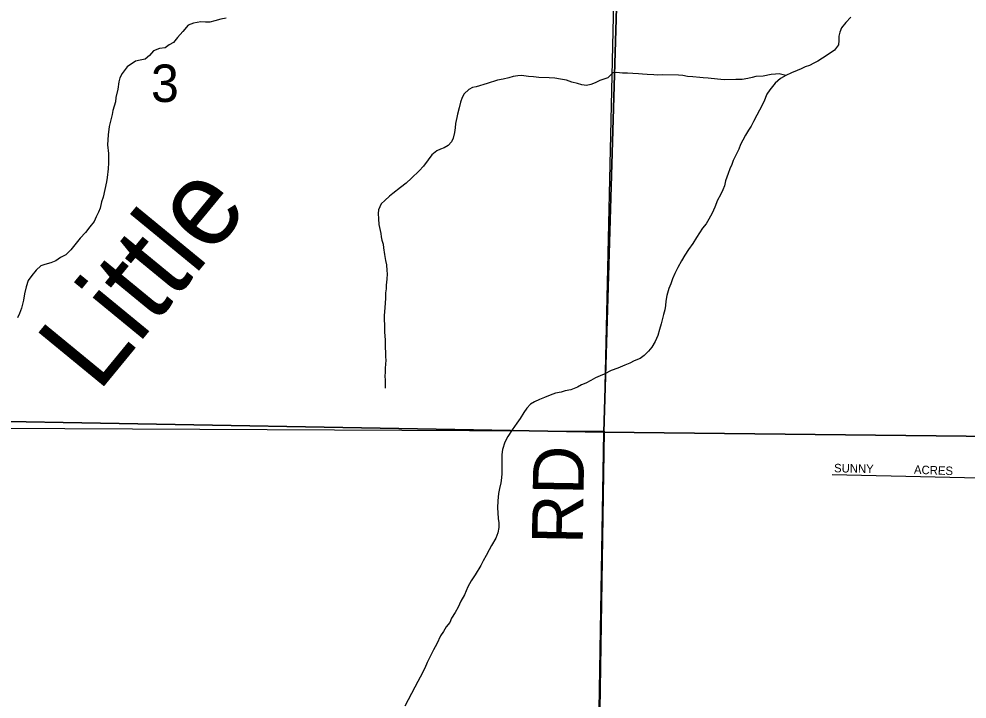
# Model space of a CAD drawing. Extents: x 1588073 to 2013523, y 1090242 to 1357120.
# Drawn here: x 1798510 to 1804101, y 1242813 to 1246824 of the extents above; entities that cross this region are included whole.
import ezdxf

# ---------------------------------------------------------------- set-up
doc = ezdxf.new("R2010")
doc.units = 0
for name, color, linetype in [('GM_X_Minor_River', 7, 'Continuous'), ('GM_X_Minor_River_Text', 7, 'Continuous'), ('GM_X_Section', 7, 'Continuous'), ('GM_X_Section_Text', 7, 'Continuous'), ('GM_X_Township', 7, 'Continuous'), ('GM_X_Township_Road', 7, 'Continuous'), ('GM_X_Township_Road_Text', 7, 'Continuous'), ('GM_X_Township_Subdivision', 7, 'Continuous'), ('GM_X_Township_Subdivision_Text', 7, 'Continuous')]:
    doc.layers.add(name, color=color, linetype=linetype)

msp = doc.modelspace()

# ---------------------------------------------------------------- linework, layer by layer
at = {"layer": 'GM_X_Minor_River'}
for points in [[(1799732.5, 1246828.6), (1799700.3, 1246823.2), (1799664, 1246813.8), (1799635.7, 1246806.3), (1799609.5, 1246804.8), (1799581.5, 1246807.3), (1799539.1, 1246800.1), (1799506.8, 1246788.6), (1799476, 1246751), (1799445.2, 1246715.4), (1799420.6, 1246685.7), (1799396.2, 1246672.1), (1799371.8, 1246654.5), (1799337.6, 1246651.1), (1799303.1, 1246635.7), (1799278.5, 1246608), (1799254, 1246586.4), (1799223.8, 1246580.9), (1799197.6, 1246575.4), (1799146.8, 1246542.2), (1799117.9, 1246502.5), (1799105.4, 1246476.6), (1799099, 1246452.6), (1799092.2, 1246410.5), (1799081.3, 1246360.5), (1799078.8, 1246336.4), (1799063.9, 1246284.4), (1799059.4, 1246260.4), (1799048.7, 1246222.4), (1799042.1, 1246190.4), (1799035.2, 1246140.3), (1799032.1, 1246082.1), (1799037.3, 1246031.7), (1799038.3, 1245975.4), (1799035.7, 1245941.3), (1799030.7, 1245889.1), (1799026.3, 1245863.1), (1799006.6, 1245773), (1798996.1, 1245745.1), (1798989.4, 1245709), (1798978.9, 1245685.1), (1798964.4, 1245657.2), (1798953.8, 1245629.3), (1798927.1, 1245597.6), (1798902.4, 1245563.9), (1798869.7, 1245530.4), (1798838.9, 1245492.8), (1798816.3, 1245463), (1798785.6, 1245433.5), (1798755.2, 1245418), (1798726.7, 1245398.4)], [(1803415.8, 1246835.5), (1803387.1, 1246803.9), (1803360.4, 1246772.2), (1803351.9, 1246746.3), (1803345.5, 1246722.3), (1803345.1, 1246698.1), (1803342.6, 1246672.1), (1803319.9, 1246640.3), (1803277.2, 1246611), (1803222.3, 1246575.8), (1803198, 1246564.2), (1803171.7, 1246550.7), (1803147.4, 1246541.1), (1803123.1, 1246529.5), (1803098.8, 1246519.9), (1803066.4, 1246506.4), (1803032, 1246491), (1803001.5, 1246473.5), (1802968.9, 1246446), (1802938, 1246406.3), (1802921.5, 1246380.5), (1802902.6, 1246334.7), (1802877.7, 1246286.9), (1802861.1, 1246257.1), (1802842.3, 1246219.2), (1802827.7, 1246191.4), (1802813.3, 1246167.5), (1802794.7, 1246139.7), (1802778.1, 1246109.9), (1802765.6, 1246084), (1802755, 1246056.1), (1802744.6, 1246032.1), (1802721.7, 1245990.3), (1802713.3, 1245966.4), (1802702.7, 1245940.5), (1802692.2, 1245912.5), (1802677.4, 1245868.6), (1802670.8, 1245840.6), (1802660.4, 1245816.6), (1802647.8, 1245786.7), (1802629.1, 1245754.9), (1802614.4, 1245715), (1802597.7, 1245679.1), (1802579, 1245643.3), (1802562.4, 1245615.5), (1802541.8, 1245589.8), (1802523.3, 1245562), (1802506.7, 1245536.1), (1802484, 1245500.4), (1802459.3, 1245464.7), (1802436.5, 1245430.9), (1802417.9, 1245397.1), (1802395.1, 1245357.4), (1802378.4, 1245323.5), (1802363.8, 1245291.6), (1802355.2, 1245261.6), (1802342.6, 1245233.7), (1802329.9, 1245193.8), (1802325.3, 1245159.7), (1802322.8, 1245133.6), (1802318.3, 1245107.6), (1802311.8, 1245081.6), (1802296.8, 1245025.6), (1802288.1, 1244991.6), (1802277.5, 1244957.6), (1802262.8, 1244921.7), (1802242.1, 1244887.9), (1802223.6, 1244864.2), (1802197, 1244838.5), (1802172.6, 1244820.9), (1802138.2, 1244807.5), (1802111.8, 1244793.9), (1802083.5, 1244782.4), (1802041, 1244765.1), (1802002.6, 1244749.7)], [(1803032, 1246491), (1802993.9, 1246499.8), (1802971.8, 1246498.2), (1802945.7, 1246496.7), (1802899.3, 1246487.5), (1802855, 1246484.3), (1802834.8, 1246478.6), (1802808.6, 1246473.1), (1802774.4, 1246467.7), (1802738.2, 1246466.4), (1802669.8, 1246465.7), (1802629.7, 1246468.4), (1802573.6, 1246475.5), (1802545.5, 1246478.1), (1802525.4, 1246478.4), (1802483.3, 1246483.3), (1802453.2, 1246485.8), (1802425.1, 1246490.4), (1802399.1, 1246492.9), (1802302.6, 1246494.7), (1802276.5, 1246493.2), (1802254.4, 1246495.6), (1802214.3, 1246496.4), (1802188.2, 1246498.9), (1802164.1, 1246501.3), (1802130, 1246502), (1802097.9, 1246504.6), (1802069.7, 1246505.1), (1802033.6, 1246507.8), (1802011.5, 1246506.2), (1801982.8, 1246476.6), (1801936.3, 1246461.4), (1801908, 1246447.9), (1801881.7, 1246438.3), (1801857.5, 1246432.8), (1801829.4, 1246435.3), (1801803.4, 1246443.8), (1801771.4, 1246452.5), (1801739.5, 1246463.1), (1801703.4, 1246469.8), (1801669.3, 1246474.5), (1801637.2, 1246477.1), (1801575, 1246478.3), (1801544.9, 1246482.9), (1801514.8, 1246485.4), (1801472.7, 1246490.3), (1801452.6, 1246488.6), (1801424.4, 1246485.1), (1801398.1, 1246477.6), (1801365.8, 1246470.2), (1801331.6, 1246462.8), (1801270.9, 1246443.8), (1801206.3, 1246424.9), (1801184.1, 1246419.3), (1801163.8, 1246407.6), (1801135.2, 1246382.1), (1801122.8, 1246360.2), (1801114.3, 1246334.2), (1801105.6, 1246300.2), (1801096.9, 1246262.2), (1801092.6, 1246242.2), (1801083.9, 1246208.2), (1801081.5, 1246182.1), (1801078.9, 1246154), (1801070.3, 1246122), (1801059.9, 1246100.1), (1801041.4, 1246078.3), (1801017.1, 1246064.7), (1800994.9, 1246057.1), (1800974.6, 1246047.4), (1800944, 1246023.9), (1800923.4, 1245994.1), (1800894.6, 1245956.5), (1800870, 1245928.8), (1800825, 1245885.4), (1800792.4, 1245855.9), (1800759.8, 1245830.4), (1800714.9, 1245795.1), (1800694.6, 1245779.4), (1800668, 1245753.7), (1800645.5, 1245734.1), (1800630.8, 1245698.2), (1800628.4, 1245676.1), (1800629.9, 1245645.9), (1800631.3, 1245611.7), (1800644.5, 1245559.2), (1800646.1, 1245539.1), (1800649.8, 1245518.9), (1800657.4, 1245496.7), (1800659, 1245474.5), (1800666.4, 1245434.2), (1800671.8, 1245399.9), (1800677.3, 1245373.7), (1800678.8, 1245341.5), (1800680.4, 1245321.4), (1800679.9, 1245289.2), (1800675.2, 1245253.1), (1800674.9, 1245233), (1800672.4, 1245209), (1800671.9, 1245176.8), (1800669.4, 1245148.7)], [(1798726.7, 1245398.4), (1798698.3, 1245384.9), (1798662, 1245375.5), (1798637.8, 1245367.9), (1798611.2, 1245342.3), (1798584.5, 1245310.6), (1798563.9, 1245280.9), (1798551.2, 1245244.9), (1798542.4, 1245202.9), (1798535.7, 1245164.8), (1798524.8, 1245118.8), (1798512.2, 1245086.9), (1798501.7, 1245061)], [(1800669.4, 1245148.7), (1800666.9, 1245122.6), (1800666.4, 1245096.5), (1800664, 1245074.4), (1800663.7, 1245054.4), (1800665, 1245016.1), (1800666.3, 1244975.9), (1800669.5, 1244931.6), (1800669.2, 1244909.6), (1800668.8, 1244887.4), (1800672.2, 1244855.2), (1800671.8, 1244831.1), (1800673.4, 1244811), (1800671, 1244788.9), (1800668.6, 1244764.8), (1800670.2, 1244738.7), (1800667.8, 1244718.6), (1800669.3, 1244692.5), (1800668.5, 1244646.3)], [(1802002.6, 1244749.7), (1801962, 1244728.4), (1801937.7, 1244718.8), (1801909.4, 1244707.3), (1801883, 1244691.7), (1801852.6, 1244676.2), (1801828.3, 1244666.6), (1801803.9, 1244653), (1801765.5, 1244637.6), (1801731.2, 1244630.2), (1801706.9, 1244622.7), (1801674.7, 1244617.2), (1801642.3, 1244605.8), (1801610, 1244592.3), (1801579.6, 1244578.8), (1801551.2, 1244565.3), (1801526.8, 1244551.7), (1801504.3, 1244528), (1801487.8, 1244502.2), (1801465.1, 1244468.4), (1801446.5, 1244440.6), (1801417.7, 1244401), (1801392.9, 1244361.3), (1801376.2, 1244327.4), (1801361.4, 1244285.5), (1801356.9, 1244255.4), (1801358.2, 1244215.2), (1801356.9, 1244142.9), (1801356.4, 1244116.7), (1801351.9, 1244088.7), (1801343.3, 1244054.7), (1801338.7, 1244024.6), (1801333.9, 1243982.5), (1801331.2, 1243940.3), (1801334.7, 1243910.1), (1801336.1, 1243877.9), (1801339.7, 1243851.8), (1801339.2, 1243823.6), (1801334.6, 1243793.6), (1801322, 1243761.6), (1801297.1, 1243717.9), (1801282.6, 1243692), (1801266, 1243660.2), (1801247.3, 1243628.4), (1801232.8, 1243600.5), (1801199.6, 1243544.9), (1801176.9, 1243509.1), (1801156.2, 1243475.3), (1801137.3, 1243427.5), (1801116.5, 1243389.7), (1801099.8, 1243353.8), (1801083.2, 1243324), (1801060.5, 1243290.2), (1801050, 1243264.3), (1801029.5, 1243238.6), (1801012.9, 1243210.7), (1800996.4, 1243184.9), (1800973.4, 1243139.1), (1800954.7, 1243103.3), (1800917.2, 1243027.6), (1800902.6, 1242993.7), (1800875.5, 1242942), (1800863, 1242916.1), (1800844.3, 1242882.3), (1800786.1, 1242770.8)]]:
    msp.add_lwpolyline(points, dxfattribs=at)
at = {"layer": 'GM_X_Section'}
for points in [[(1796800, 1249618.5), (1796832, 1249616.2), (1802113, 1249526.3), (1801959.1, 1244386.1), (1796680.8, 1244482.2)], [(1802113, 1249526.3), (1807479.7, 1249429), (1807302, 1244327), (1801959.1, 1244386.1)], [(1796680.8, 1244482.2), (1801959.1, 1244386.1), (1801870.6, 1239129.5), (1801854.6, 1239129.6), (1796560.6, 1239208)]]:
    msp.add_lwpolyline(points, close=True, dxfattribs=at)
msp.add_lwpolyline([(1804130.7, 1239253.6), (1804058.1, 1239160), (1804011.7, 1239102.2), (1803981.7, 1239104.4), (1801870.6, 1239129.5), (1801959.1, 1244386.1), (1807302, 1244327)], dxfattribs=at)
at = {"layer": 'GM_X_Township'}
msp.add_lwpolyline([(1797984.2, 1244413.4), (1801960.9, 1244391.9), (1801920.6, 1241735), (1801890.5, 1240139), (1801887.2, 1239964.3), (1801886.9, 1239947.5), (1801886.6, 1239927.4), (1801885.9, 1239884.3), (1801873.5, 1239136.1), (1802319.3, 1239134.2), (1804310.1, 1239084)], dxfattribs=at)
msp.add_lwpolyline([(1797984.2, 1244413.4), (1801960.9, 1244391.9), (1801920.6, 1241735), (1801890.5, 1240139), (1801887.2, 1239964.3), (1801886.9, 1239947.5), (1801886.6, 1239927.4), (1801885.9, 1239884.3), (1801873.5, 1239136.1), (1802319.3, 1239134.2), (1804310.1, 1239084)], dxfattribs=at)
at = {"layer": 'GM_X_Township_Road'}
msp.add_lwpolyline([(1801920.6, 1241735), (1801960.9, 1244391.9), (1802019.4, 1247015.1)], dxfattribs=at)
at = {"layer": 'GM_X_Township_Subdivision'}
msp.add_lwpolyline([(1803306.6, 1244136.9), (1804607.5, 1244107.2)], dxfattribs=at)

# ---------------------------------------------------------------- texts
at = {"layer": 'GM_X_Minor_River_Text'}
msp.add_text('Little', height=500.31, rotation=50.5945, dxfattribs=at).set_placement((1798976.4, 1244615))
at = {"layer": 'GM_X_Section_Text'}
msp.add_text('3', height=221, rotation=0, dxfattribs=at).set_placement((1799288.2, 1246334.7))
at = {"layer": 'GM_X_Township_Road_Text'}
msp.add_text('RD', height=300, rotation=89.0128, dxfattribs=at).set_placement((1801834.4, 1243725))
at = {"layer": 'GM_X_Township_Subdivision_Text'}
for s, rotation, p in [('SUNNY', 358.8072, (1803316.6, 1244150.4)), ('ACRES', 357.9186, (1803787.6, 1244141.6))]:
    msp.add_text(s, height=50, rotation=rotation, dxfattribs=at).set_placement(p)

doc.saveas('drawing.dxf')
